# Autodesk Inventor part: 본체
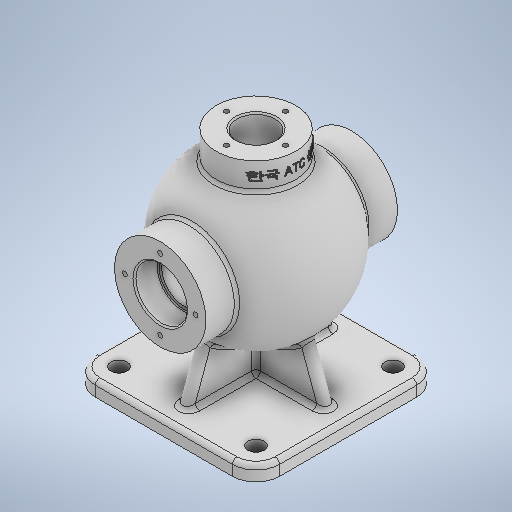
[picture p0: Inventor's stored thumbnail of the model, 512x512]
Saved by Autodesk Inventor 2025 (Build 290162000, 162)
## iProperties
Created: 2024-07
Part Number: 본체
Material: 일반
Document SubType Name: Modeling
Designer: deana
Density: 1 g/cm^3
Appearance: 기본값
Author: deana
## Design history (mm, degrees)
sketch "스케치1"
  geometry: L1 (46.5, -62.5)-(-46.5, -62.5); L2 (-62.5, -46.5)-(-62.5, 46.5); L3 (-46.5, 62.5)-(46.5, 62.5); L4 (62.5, 46.5)-(62.5, -46.5); L5 (62.5, -62.5)-(-62.5, 62.5); L6 (-62.5, -62.5)-(62.5, 62.5); C1 r 5.5 at (46.5, -46.5); C2 r 5.5 at (-46.5, -46.5); C3 r 5.5 at (46.5, 46.5); C4 r 5.5 at (-46.5, 46.5); A1 r 16 centre (46.5, -46.5) between (46.5, -62.5) and (62.5, -46.5); A2 r 16 centre (-46.5, -46.5) between (-62.5, -46.5) and (-46.5, -62.5); A3 r 16 centre (-46.5, 46.5) between (-46.5, 62.5) and (-62.5, 46.5); A4 r 16 centre (46.5, 46.5) between (62.5, 46.5) and (46.5, 62.5); 1 further point
  constraints: 12 end point, 8 centre point, 8 point on circle, 8 point on line, 8 tangent, 4 coincident, 3 equal radius, 2 midpoint, 2 parallel, 1 horizontal, 1 perpendicular
  dimensions: "d0" = 125 distance of L5.end L6.end; "d1" = 125 distance of L6.start L5.end; "d2" = 16 radius of A1; "d3" = 11 diameter of C1; "d4" = 11 diameter of C2; "d5" = 11 diameter of C3; "d6" = 11 diameter of C4
extrude "돌출1" new body sketch "스케치1" distance "d7" = 10; taper "d8" = 0 deg
sketch "스케치2"
  geometry: L1 (0, 46.5)-(0, -46.5) reference; L2 (139, 0)-(31, 0); L3 (139, 0)-(31, 0); A1 r 54 centre (85, 0) between (31, 0) and (139, 0); A2 r 54 centre (85, 0) between (139, 0) and (31, 0); 4 further points
  constraints: 5 point on circle, 4 end point, 3 midpoint, 2 centre point, 1 coincident, 1 collinear, 1 horizontal, 1 horizontal alignment
  dimensions: "d10" = 108 diameter of A1; "d11" = 85 distance of point (0, 0) A1.centre
revolve "회전1" sketch "스케치2" stored, may be unused: angle "d12" = 90 deg
sketch "스케치3"
  geometry: C1 r 31 at (0, 85); 1 further point
  constraints: 1 centre point, 1 vertical alignment
  dimensions: "d13" = 62 diameter of C1; "d14" = 85 distance of point (0, 0) C1.centre
extrude "돌출2" join sketch "스케치3" stored distance "d15" = 130; taper "d16" = 0 deg
node "작업 평면1"
sketch "스케치7"
  geometry: C1 r 27 at (0, 0); C2 r 13 at (0, 0); 1 further point
  constraints: 2 centre point, 2 coincident
  dimensions: "d43" = 54 diameter of C1; "d44" = 26 diameter of C2
extrude "돌출3" join sketch "스케치7" distance "d45" = 65; taper "d46" = 0 deg
sketch "스케치4"
  geometry: C1 r 31 at (0, 0) reference; 2 further points
  constraints: 1 coincident
hole "구멍1" sketch "스케치4" at (0, 0) diameter "d17" = 30; stored, may be unused: countersink angle "d21" = 90 deg, drill point angle "d23" = 0 deg; dims "d18" = 6, "d19" = 4, "d20" = 2, "d22" = 30
sketch "스케치5"
  geometry: C1 r 31 at (0, 0) reference; 2 further points
  constraints: 1 coincident
hole "구멍2" sketch "스케치5" at (0, 0) diameter "d24" = 35; stored, may be unused: countersink angle "d28" = 90 deg, drill point angle "d30" = 0 deg; dims "d25" = 6, "d26" = 4, "d27" = 2, "d29" = 16
sketch "스케치6"
  geometry: C1 r 31 at (0, 0) reference; 2 further points
  constraints: 1 coincident
hole "구멍3" sketch "스케치6" at (0, 0) diameter "d31" = 35; stored, may be unused: countersink angle "d35" = 90 deg, drill point angle "d37" = 0 deg; dims "d32" = 6, "d33" = 4, "d34" = 2, "d36" = 16
fillet "모깎기2" dims "d38" = 0.6
chamfer "모따기1" distance "d39" = 1; stored, may be unused: second distance "d40" = 2, angle "d41" = 45 deg
extrude "돌출4" cut sketch "스케치7" distance "d47" = 65; taper "d48" = 0 deg
fillet "모깎기3" dims "d49" = 3
chamfer "모따기2" distance "d50" = 1; stored, may be unused: second distance "d51" = 2, angle "d52" = 45 deg
sketch "스케치8"
  geometry: L1 (57.519, 33.204)-(10, 50.5); L2 (10, 50.5)-(10, -50.5); L3 (10, -50.5)-(57.519, -33.204); L4 (57.519, -33.204)-(57.519, 33.204); L5 (10, 0)-(89.28, 0); L6 (0, -62.5)-(10, -62.5) reference; L7 (10, 46.5)-(10, -46.5) reference; 1 further point
  constraints: 10 end point, 1 collinear, 1 horizontal alignment, 1 midpoint, 1 parallel, 1 perpendicular, 1 vertical, 1 other
  dimensions: "d53" = 12 distance of L6.end L2.end; "d55" = 20 deg angle of L6 L3; "d56" = 47.51942 distance between parallel lines of L2 L4
extrude "돌출5" join sketch "스케치8" stored distance "d57" = 8; taper "d58" = 0 deg
sketch "스케치12"
  geometry: L1 (-32.966, 58.173)-(-50.5, 10); L2 (-50.5, 10)-(50.5, 10); L3 (50.5, 10)-(32.966, 58.173); L4 (32.966, 58.173)-(-32.966, 58.173); L5 (46.5, 0)-(-46.5, 0) reference; L6 (0, 0)-(0, 70); L7 (46.5, 10)-(-46.5, 10) reference; L8 (62.5, 0)-(62.5, 10) reference; 1 further point
  constraints: 10 end point, 1 collinear, 1 horizontal, 1 parallel, 1 vertical, 1 vertical alignment, 2 other
  dimensions: "d63" = 12 distance of L8.end L2.end; "d64" = 20 deg angle of L8 L3; "d65" = 48.1733 distance between parallel lines of L2 L4
extrude "돌출6" join sketch "스케치12" stored distance "d66" = 8; taper "d67" = 0 deg
feature "전체 둥근 모깎기1"
feature "전체 둥근 모깎기2"
feature "전체 둥근 모깎기3"
feature "전체 둥근 모깎기4"
fillet "모깎기4" dims "d68" = 3
fillet "모깎기5" dims "d69" = 3
node "작업 평면2"
sketch "스케치13"
  geometry: L1 (150, -27)-(150, 27) reference; 2 further points
  constraints: 1 horizontal alignment, 1 other
  dimensions: "d71" = 9 distance from line of L1 point (141, 0)
feature "엠보싱1" sketch "스케치13" dims "d72" = 0.5, "d73" = 0
fillet "모깎기6" dims "d74" = 3
fillet "모깎기7" dims "d75" = 3
fillet "모깎기8" dims "d76" = 3
sketch "스케치14" dims "d84" = 48
  geometry: C1 r 31 at (0, 0) reference; C2 r 15 at (0, 0) reference; 3 further points
  constraints: 2 vertical alignment, 1 coincident, 2 other
hole "구멍4" sketch "스케치14" at (0, 24) diameter "d77" = 3.242; stored, may be unused: countersink angle "d81" = 90 deg, drill point angle "d83" = 120 deg; dims "d78" = 12, "d79" = 4, "d80" = 2, "d82" = 15
sketch "스케치15" dims "d95" = 40
  geometry: 3 further points
  constraints: 2 horizontal alignment, 1 coincident, 2 other
hole "구멍5" sketch "스케치15" at (-20, 0) diameter "d88" = 3.242; stored, may be unused: countersink angle "d92" = 90 deg, drill point angle "d94" = 120 deg; dims "d89" = 9, "d90" = 4, "d91" = 2, "d93" = 11
node "솔리드1"
pattern_circular "원형 패턴1" dims angle "d86" = 360 deg
mirror "미러1"
pattern_circular "원형 패턴2" dims angle "d97" = 360 deg
feature "A9D066F2-1C7D-4E18-AEED-F7BC21143FA4" dims "d17" = 30, "d18" = 6, "d19" = 4, "d20" = 2, "d21" = 90 deg, "d22" = 30, "d23" = 0
other parameters: "d42" = 85
